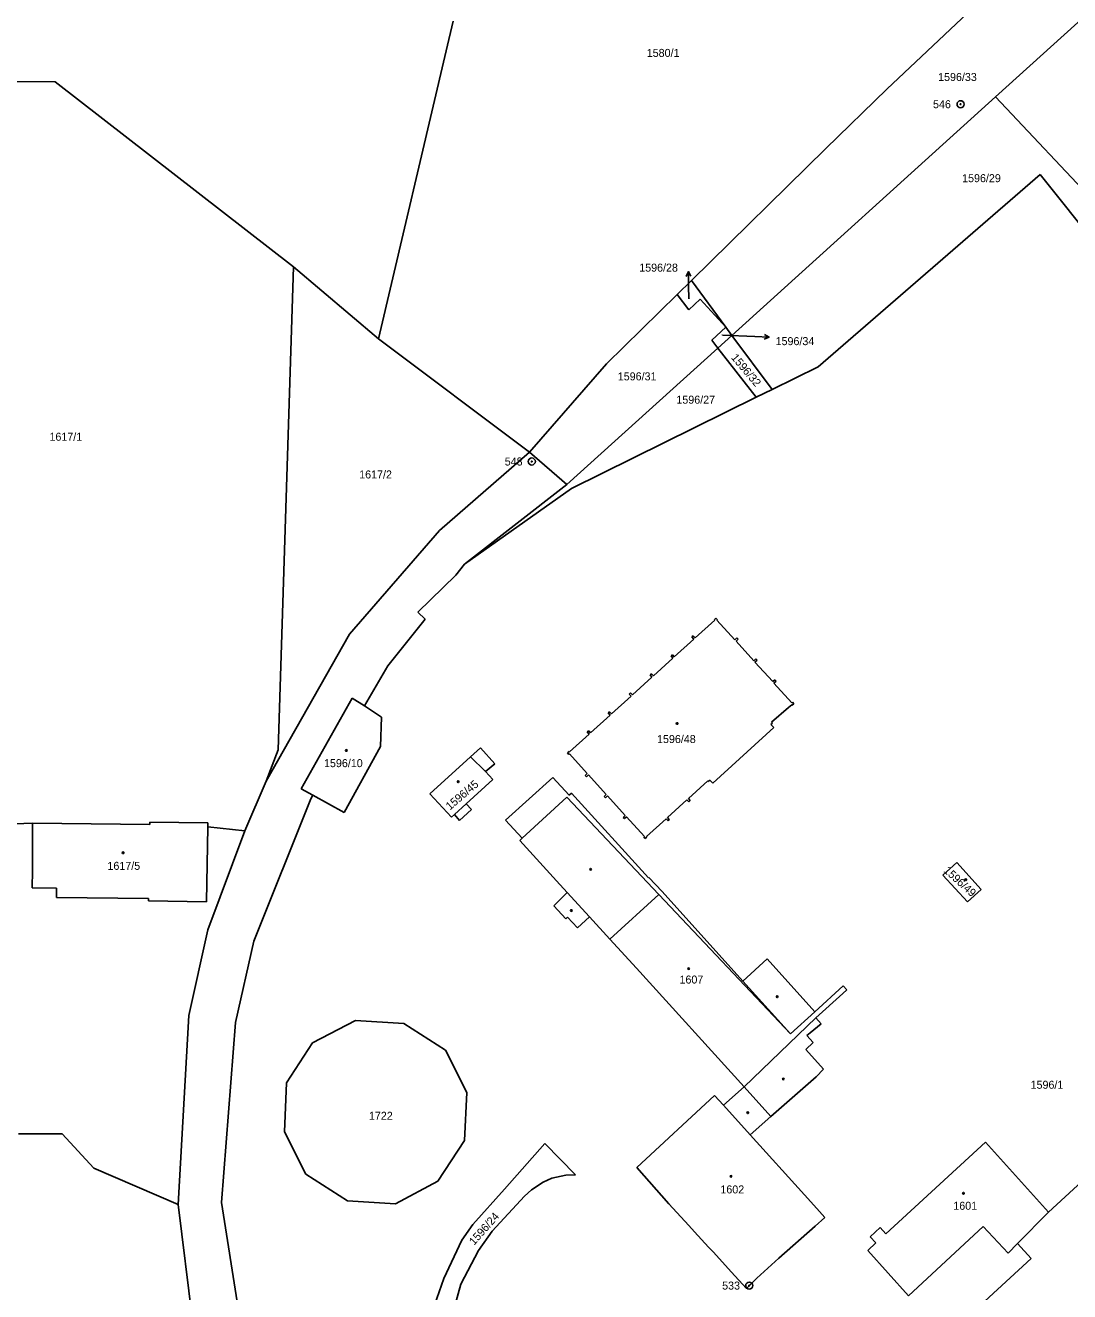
# Model space of a CAD drawing. Extents: x -763296 to -761805, y -1153670 to -1152034.
# Drawn here: x -762540.8 to -762319, y -1152808 to -1152539 of the extents above; entities that cross this region are included whole.
import ezdxf

# ---------------------------------------------------------------- set-up
doc = ezdxf.new("R2010")
doc.units = 0
for name, color, linetype in [('Vrstva 1', 7, 'Continuous'), ('Vrstva 16', 7, 'Continuous'), ('Vrstva 17', 7, 'Continuous'), ('Vrstva 18', 7, 'Continuous'), ('Vrstva 19', 7, 'Continuous'), ('Vrstva 24', 7, 'Continuous'), ('Vrstva 25', 7, 'Continuous'), ('Vrstva 4', 7, 'Continuous')]:
    doc.layers.add(name, color=color, linetype=linetype)

msp = doc.modelspace()

# ---------------------------------------------------------------- linework, layer by layer
at = {"layer": 'Vrstva 1'}
for p, q in [((-762281.64, -1152506.08), (-762334.74, -1152554.22)), ((-762357.84, -1152552.56), (-762327.69, -1152524.15)), ((-762451.46, -1152544.43), (-762449.99, -1152538.18)), ((-762465.85, -1152605.61), (-762451.46, -1152544.43)), ((-762563.28, -1152550.87), (-762534.53, -1152551.03)), ((-762534.53, -1152551.03), (-762483.9, -1152590.32)), ((-762370.78, -1152565.17), (-762357.84, -1152552.56)), ((-762334.74, -1152554.22), (-762390.74, -1152604.87)), ((-762334.74, -1152554.22), (-762311.03, -1152579.45)), ((-762399.32, -1152593.19), (-762370.78, -1152565.17)), ((-762372.45, -1152611.55), (-762325.29, -1152570.73)), ((-762325.29, -1152570.73), (-762304.85, -1152596.27)), ((-762483.9, -1152590.32), (-762487.15, -1152692.86)), ((-762483.9, -1152590.32), (-762465.85, -1152605.61)), ((-762399.32, -1152593.19), (-762402.39, -1152596.21)), ((-762399.32, -1152593.19), (-762392.03, -1152603.14)), ((-762402.39, -1152596.21), (-762417.4, -1152610.95)), ((-762399.93, -1152599.44), (-762402.39, -1152596.21)), ((-762397.51, -1152597.2), (-762399.93, -1152599.44)), ((-762397.51, -1152597.2), (-762392.03, -1152603.14)), ((-762395.01, -1152605.89), (-762392.03, -1152603.14)), ((-762390.74, -1152604.87), (-762393.71, -1152607.56)), ((-762392.03, -1152603.14), (-762390.74, -1152604.87)), ((-762390.74, -1152604.87), (-762382.19, -1152616.35)), ((-762465.85, -1152605.61), (-762433.74, -1152629.71)), ((-762393.71, -1152607.56), (-762425.78, -1152636.56)), ((-762393.71, -1152607.56), (-762395.01, -1152605.89)), ((-762385.59, -1152618.03), (-762393.71, -1152607.56)), ((-762417.4, -1152610.95), (-762433.74, -1152629.71)), ((-762382.19, -1152616.35), (-762372.45, -1152611.55)), ((-762424.84, -1152637.36), (-762385.59, -1152618.03)), ((-762385.59, -1152618.03), (-762382.19, -1152616.35)), ((-762433.74, -1152629.71), (-762452.83, -1152646.28)), ((-762425.78, -1152636.56), (-762433.74, -1152629.71)), ((-762425.78, -1152636.56), (-762447.55, -1152653.45)), ((-762447.55, -1152653.45), (-762424.84, -1152637.36)), ((-762452.83, -1152646.28), (-762472.01, -1152668.31)), ((-762447.55, -1152653.45), (-762449.4, -1152655.83)), ((-762449.4, -1152655.83), (-762457.48, -1152663.67)), ((-762457.48, -1152663.67), (-762455.94, -1152665.15)), ((-762455.94, -1152665.15), (-762463.84, -1152675.06)), ((-762394.37, -1152665.32), (-762398.54, -1152669.12)), ((-762394.14, -1152664.93), (-762394.47, -1152665.21)), ((-762394.47, -1152665.21), (-762394.37, -1152665.32)), ((-762393.84, -1152665.25), (-762394.14, -1152664.93)), ((-762393.95, -1152665.35), (-762393.84, -1152665.25)), ((-762390.13, -1152669.53), (-762393.95, -1152665.35)), ((-762472.01, -1152668.31), (-762489.68, -1152699.53)), ((-762398.85, -1152669.38), (-762402.98, -1152673.15)), ((-762398.95, -1152668.69), (-762399.24, -1152668.93)), ((-762399.24, -1152668.93), (-762398.85, -1152669.38)), ((-762398.54, -1152669.12), (-762398.95, -1152668.69)), ((-762389.69, -1152669.13), (-762390.13, -1152669.53)), ((-762389.87, -1152669.82), (-762389.43, -1152669.41)), ((-762389.43, -1152669.41), (-762389.69, -1152669.13)), ((-762386.12, -1152673.97), (-762389.87, -1152669.82)), ((-762463.84, -1152675.06), (-762468.82, -1152683.56)), ((-762403.29, -1152673.42), (-762407.42, -1152677.19)), ((-762403.38, -1152672.72), (-762403.67, -1152672.96)), ((-762403.67, -1152672.96), (-762403.29, -1152673.42)), ((-762402.98, -1152673.15), (-762403.38, -1152672.72)), ((-762385.67, -1152673.58), (-762386.12, -1152673.97)), ((-762385.85, -1152674.27), (-762385.41, -1152673.86)), ((-762382.08, -1152678.41), (-762385.85, -1152674.27)), ((-762385.41, -1152673.86), (-762385.67, -1152673.58)), ((-762407.73, -1152677.45), (-762411.87, -1152681.22)), ((-762407.83, -1152676.76), (-762408.12, -1152677)), ((-762408.12, -1152677), (-762407.73, -1152677.45)), ((-762407.42, -1152677.19), (-762407.83, -1152676.76)), ((-762381.65, -1152678.01), (-762382.08, -1152678.41)), ((-762381.81, -1152678.71), (-762381.38, -1152678.29)), ((-762378.02, -1152682.9), (-762381.81, -1152678.71)), ((-762381.38, -1152678.29), (-762381.65, -1152678.01)), ((-762482.24, -1152701.14), (-762471.39, -1152681.91)), ((-762471.39, -1152681.91), (-762468.82, -1152683.56)), ((-762412.18, -1152681.48), (-762416.32, -1152685.25)), ((-762412.28, -1152680.79), (-762412.57, -1152681.04)), ((-762412.57, -1152681.04), (-762412.18, -1152681.48)), ((-762411.87, -1152681.22), (-762412.28, -1152680.79)), ((-762377.9, -1152682.8), (-762378.02, -1152682.9)), ((-762377.95, -1152683.41), (-762377.62, -1152683.11)), ((-762377.62, -1152683.11), (-762377.9, -1152682.8)), ((-762468.82, -1152683.56), (-762465.15, -1152685.93)), ((-762416.63, -1152685.52), (-762420.76, -1152689.28)), ((-762416.72, -1152684.81), (-762417.02, -1152685.06)), ((-762417.02, -1152685.06), (-762416.63, -1152685.52)), ((-762416.32, -1152685.25), (-762416.72, -1152684.81)), ((-762382.33, -1152687.01), (-762378.74, -1152683.92)), ((-762378.74, -1152683.92), (-762378.04, -1152683.31)), ((-762378.04, -1152683.31), (-762377.95, -1152683.41)), ((-762465.15, -1152685.93), (-762465.37, -1152692.18)), ((-762394.82, -1152699.95), (-762381.86, -1152688.18)), ((-762382.47, -1152687.54), (-762382.13, -1152687.24)), ((-762381.86, -1152688.18), (-762382.47, -1152687.54)), ((-762382.13, -1152687.24), (-762382.33, -1152687.01)), ((-762421.07, -1152689.54), (-762425.23, -1152693.35)), ((-762421.16, -1152688.83), (-762421.46, -1152689.09)), ((-762421.46, -1152689.09), (-762421.07, -1152689.54)), ((-762420.76, -1152689.28), (-762421.16, -1152688.83)), ((-762487.15, -1152692.86), (-762489.68, -1152699.53)), ((-762465.37, -1152692.18), (-762473.14, -1152706.19)), ((-762446.26, -1152694.38), (-762444.18, -1152692.48)), ((-762444.18, -1152692.48), (-762441.09, -1152695.84)), ((-762425.34, -1152693.24), (-762425.67, -1152693.52)), ((-762425.67, -1152693.52), (-762425.39, -1152693.85)), ((-762425.39, -1152693.85), (-762425.26, -1152693.76)), ((-762425.23, -1152693.35), (-762425.34, -1152693.24)), ((-762425.26, -1152693.76), (-762421.48, -1152697.95)), ((-762454.88, -1152702.24), (-762446.26, -1152694.38)), ((-762441.09, -1152695.84), (-762443.07, -1152697.52)), ((-762441.54, -1152699.2), (-762447.19, -1152704.36)), ((-762443.07, -1152697.52), (-762441.54, -1152699.2)), ((-762428.78, -1152698.75), (-762438.83, -1152707.85)), ((-762425.34, -1152702.54), (-762428.78, -1152698.75)), ((-762421.48, -1152697.95), (-762421.91, -1152698.35)), ((-762421.91, -1152698.35), (-762421.65, -1152698.63)), ((-762421.65, -1152698.63), (-762421.21, -1152698.23)), ((-762421.21, -1152698.23), (-762417.46, -1152702.38)), ((-762395.76, -1152699.62), (-762395.43, -1152699.3)), ((-762395.43, -1152699.3), (-762394.82, -1152699.95)), ((-762489.68, -1152699.53), (-762494.2, -1152710.06)), ((-762479.75, -1152702.52), (-762482.24, -1152701.14)), ((-762399.99, -1152703.22), (-762395.86, -1152699.5)), ((-762395.86, -1152699.5), (-762395.76, -1152699.62)), ((-762492.32, -1152733.53), (-762480.19, -1152703.28)), ((-762480.19, -1152703.28), (-762479.75, -1152702.52)), ((-762473.14, -1152706.19), (-762479.75, -1152702.52)), ((-762450.31, -1152707.21), (-762454.88, -1152702.24)), ((-762447.19, -1152704.36), (-762446.06, -1152705.59)), ((-762424.84, -1152702.12), (-762425.34, -1152702.54)), ((-762408.46, -1152720.09), (-762424.84, -1152702.12)), ((-762417.46, -1152702.38), (-762417.88, -1152702.79)), ((-762417.88, -1152702.79), (-762417.61, -1152703.07)), ((-762417.61, -1152703.07), (-762417.18, -1152702.67)), ((-762417.18, -1152702.67), (-762413.42, -1152706.84)), ((-762404.44, -1152707.25), (-762400.3, -1152703.49)), ((-762400.3, -1152703.49), (-762399.9, -1152703.94)), ((-762399.61, -1152703.68), (-762399.99, -1152703.22)), ((-762399.9, -1152703.94), (-762399.61, -1152703.68)), ((-762449.7, -1152706.66), (-762450.31, -1152707.21)), ((-762448.58, -1152707.88), (-762449.7, -1152706.66)), ((-762446.06, -1152705.59), (-762448.58, -1152707.88)), ((-762413.42, -1152706.84), (-762413.84, -1152707.24)), ((-762413.84, -1152707.24), (-762413.59, -1152707.51)), ((-762413.59, -1152707.51), (-762413.14, -1152707.12)), ((-762413.14, -1152707.12), (-762409.35, -1152711.3)), ((-762404.05, -1152707.71), (-762404.44, -1152707.25)), ((-762539.34, -1152708.5), (-762546.77, -1152708.77)), ((-762514.4, -1152708.72), (-762539.34, -1152708.5)), ((-762539.34, -1152708.5), (-762539.32, -1152718.51)), ((-762514.39, -1152708.22), (-762514.4, -1152708.72)), ((-762502.07, -1152708.43), (-762514.39, -1152708.22)), ((-762502.38, -1152725.17), (-762502.09, -1152709.28)), ((-762502.09, -1152709.28), (-762502.07, -1152708.43)), ((-762494.2, -1152710.06), (-762502.09, -1152709.28)), ((-762502.04, -1152731.13), (-762494.2, -1152710.06)), ((-762438.83, -1152707.85), (-762435.29, -1152711.67)), ((-762408.91, -1152711.32), (-762404.73, -1152707.52)), ((-762404.73, -1152707.52), (-762404.31, -1152707.95)), ((-762404.31, -1152707.95), (-762404.05, -1152707.71)), ((-762435.8, -1152712.14), (-762435.29, -1152711.67)), ((-762428.02, -1152720.7), (-762435.8, -1152712.14)), ((-762409.35, -1152711.3), (-762409.44, -1152711.4)), ((-762409.44, -1152711.4), (-762409.14, -1152711.72)), ((-762409.14, -1152711.72), (-762408.83, -1152711.44)), ((-762408.83, -1152711.44), (-762408.91, -1152711.32)), ((-762345.91, -1152719.48), (-762342.99, -1152716.85)), ((-762342.99, -1152716.85), (-762337.77, -1152722.58)), ((-762539.32, -1152718.51), (-762539.38, -1152722.19)), ((-762425.74, -1152723.19), (-762428.02, -1152720.7)), ((-762408.36, -1152720.01), (-762408.46, -1152720.09)), ((-762405.58, -1152723), (-762408.36, -1152720.01)), ((-762340.67, -1152725.2), (-762345.91, -1152719.48)), ((-762539.38, -1152722.19), (-762534.2, -1152722.27)), ((-762534.2, -1152722.27), (-762534.23, -1152724.25)), ((-762425.74, -1152723.19), (-762428.57, -1152725.99)), ((-762388.45, -1152741.99), (-762405.58, -1152723)), ((-762337.77, -1152722.58), (-762340.67, -1152725.2)), ((-762534.23, -1152724.25), (-762514.66, -1152724.44)), ((-762514.66, -1152724.44), (-762514.67, -1152724.97)), ((-762514.67, -1152724.97), (-762502.38, -1152725.17)), ((-762428.57, -1152725.99), (-762426, -1152728.75)), ((-762426, -1152728.75), (-762425.64, -1152728.42)), ((-762425.64, -1152728.42), (-762423.58, -1152730.67)), ((-762423.58, -1152730.67), (-762421.03, -1152728.33)), ((-762416.67, -1152733.1), (-762421.03, -1152728.33)), ((-762506.09, -1152749.33), (-762502.04, -1152731.13)), ((-762492.32, -1152733.53), (-762496.17, -1152750.77)), ((-762416.67, -1152733.1), (-762411, -1152739.29)), ((-762411, -1152739.29), (-762388.13, -1152764.44)), ((-762383.24, -1152737.28), (-762388.45, -1152741.99)), ((-762373.11, -1152748.52), (-762383.24, -1152737.28)), ((-762367.09, -1152743.02), (-762373.11, -1152748.52)), ((-762372.91, -1152749.82), (-762367.17, -1152744.61)), ((-762367.17, -1152744.61), (-762366.35, -1152743.86)), ((-762366.35, -1152743.86), (-762367.09, -1152743.02)), ((-762508.36, -1152789.42), (-762506.09, -1152749.33)), ((-762470.69, -1152750.4), (-762479.81, -1152755.1)), ((-762460.47, -1152751), (-762470.69, -1152750.4)), ((-762371.79, -1152751.06), (-762372.91, -1152749.82)), ((-762496.17, -1152750.77), (-762499.2, -1152789.04)), ((-762460.47, -1152751), (-762451.62, -1152756.7)), ((-762374.82, -1152753.54), (-762374.12, -1152752.96)), ((-762374.12, -1152752.96), (-762371.79, -1152751.06)), ((-762479.81, -1152755.1), (-762485.39, -1152763.63)), ((-762375.07, -1152756.55), (-762373.51, -1152755.04)), ((-762373.51, -1152755.04), (-762374.82, -1152753.54)), ((-762451.62, -1152756.7), (-762447.02, -1152765.68)), ((-762371.31, -1152760.71), (-762375.07, -1152756.55)), ((-762372.87, -1152762.36), (-762371.31, -1152760.71)), ((-762485.39, -1152763.63), (-762485.82, -1152774)), ((-762382.45, -1152770.73), (-762372.87, -1152762.36)), ((-762447.02, -1152765.68), (-762447.54, -1152775.89)), ((-762410.91, -1152781.62), (-762394.44, -1152766.33)), ((-762394.44, -1152766.33), (-762392.51, -1152768.38)), ((-762388.13, -1152764.44), (-762392.51, -1152768.38)), ((-762392.51, -1152768.38), (-762386.84, -1152774.68)), ((-762386.84, -1152774.68), (-762382.45, -1152770.73)), ((-762532.99, -1152774.42), (-762542.3, -1152774.42)), ((-762526.31, -1152781.74), (-762532.99, -1152774.42)), ((-762485.82, -1152774), (-762481.28, -1152783)), ((-762323.47, -1152791.06), (-762304.18, -1152773.27)), ((-762447.54, -1152775.89), (-762453.19, -1152784.48)), ((-762439.08, -1152786.17), (-762430.49, -1152776.49)), ((-762430.49, -1152776.49), (-762423.95, -1152783.13)), ((-762386.84, -1152774.68), (-762375.36, -1152787.41)), ((-762358.06, -1152795.67), (-762336.9, -1152776.19)), ((-762336.9, -1152776.19), (-762323.47, -1152791.06)), ((-762508.36, -1152789.42), (-762526.31, -1152781.74)), ((-762404.12, -1152789.3), (-762410.91, -1152781.62)), ((-762481.28, -1152783), (-762472.43, -1152788.7)), ((-762462.21, -1152789.3), (-762453.19, -1152784.48)), ((-762430.82, -1152784.7), (-762433.34, -1152786.3)), ((-762428.97, -1152783.85), (-762430.82, -1152784.7)), ((-762426, -1152783.24), (-762428.97, -1152783.85)), ((-762423.95, -1152783.13), (-762426, -1152783.24)), ((-762445.79, -1152793.67), (-762439.08, -1152786.17)), ((-762434.84, -1152787.68), (-762441.66, -1152795.08)), ((-762433.34, -1152786.3), (-762434.84, -1152787.68)), ((-762375.36, -1152787.41), (-762372.72, -1152790.32)), ((-762508.36, -1152789.42), (-762504.64, -1152819.5)), ((-762499.2, -1152789.04), (-762495.62, -1152811.48)), ((-762472.43, -1152788.7), (-762462.21, -1152789.3)), ((-762399.9, -1152793.94), (-762404.12, -1152789.3)), ((-762372.72, -1152790.32), (-762371.03, -1152792.19)), ((-762371.03, -1152792.19), (-762373.07, -1152794.05)), ((-762323.47, -1152791.06), (-762330.08, -1152797.75)), ((-762448.1, -1152797.01), (-762445.79, -1152793.67)), ((-762441.66, -1152795.08), (-762444.61, -1152799.19)), ((-762398.69, -1152795.27), (-762399.9, -1152793.94)), ((-762395.72, -1152798.53), (-762398.69, -1152795.27)), ((-762373.07, -1152794.05), (-762380.8, -1152800.84)), ((-762361.38, -1152796.29), (-762359.29, -1152794.34)), ((-762359.29, -1152794.34), (-762358.06, -1152795.67)), ((-762337.37, -1152794.13), (-762353.25, -1152808.84)), ((-762332.1, -1152799.8), (-762337.37, -1152794.13)), ((-762451.93, -1152805.15), (-762448.1, -1152797.01)), ((-762394.69, -1152799.57), (-762395.72, -1152798.53)), ((-762361.9, -1152799.22), (-762360.15, -1152797.61)), ((-762360.15, -1152797.61), (-762361.38, -1152796.29)), ((-762330.08, -1152797.75), (-762332.1, -1152799.8)), ((-762330.08, -1152797.75), (-762327.17, -1152800.94)), ((-762444.61, -1152799.19), (-762448.3, -1152806.34)), ((-762390.93, -1152803.73), (-762394.69, -1152799.57)), ((-762380.8, -1152800.84), (-762385.46, -1152805.08)), ((-762353.25, -1152808.84), (-762361.9, -1152799.22)), ((-762349.07, -1152820.98), (-762327.17, -1152800.94)), ((-762387.68, -1152807.32), (-762390.93, -1152803.73)), ((-762453.95, -1152810.83), (-762451.93, -1152805.15)), ((-762448.3, -1152806.34), (-762450.74, -1152815.01)), ((-762385.46, -1152805.08), (-762387.68, -1152807.32))]:
    msp.add_line(p, q, dxfattribs=at)
at = {"layer": 'Vrstva 16'}
for p, q in [((-762399.991, -1152591.34), (-762399.94, -1152594.34)), ((-762399.89, -1152597.09), (-762399.94, -1152594.34)), ((-762392.73, -1152604.85), (-762385.86, -1152605.13)), ((-762382.862, -1152605.251), (-762385.86, -1152605.13))]:
    msp.add_line(p, q, dxfattribs=at)
for points in [[(-762400.474, -1152592.349), (-762399.991, -1152591.34), (-762399.474, -1152592.332)], [(-762383.841, -1152604.711), (-762382.862, -1152605.251), (-762383.882, -1152605.71)]]:
    msp.add_lwpolyline(points, dxfattribs=at)
at = {"layer": 'Vrstva 24'}
for centre, radius in [((-762342.18, -1152555.78), 0.75), ((-762342.18, -1152555.78), 0.1), ((-762433.25, -1152631.66), 0.75), ((-762433.25, -1152631.66), 0.1), ((-762387.07, -1152806.67), 0.75), ((-762387.07, -1152806.67), 0.1)]:
    msp.add_circle(centre, radius, dxfattribs=at)
at = {"layer": 'Vrstva 25'}
for centre in [(-762402.39, -1152687.3), (-762472.66, -1152693.02), (-762448.88, -1152699.66), (-762520.07, -1152714.75), (-762420.76, -1152718.26), (-762341.07, -1152720.47), (-762424.87, -1152727.02), (-762399.95, -1152739.35), (-762381.13, -1152745.32), (-762379.81, -1152762.8), (-762387.37, -1152769.96), (-762390.95, -1152783.47), (-762341.57, -1152787.06)]:
    msp.add_circle(centre, 0.175, dxfattribs=at)
at = {"layer": 'Vrstva 4'}
for p, q in [((-762446.26, -1152694.38), (-762443.07, -1152697.52)), ((-762447.19, -1152704.36), (-762449.7, -1152706.66)), ((-762425.8, -1152702.94), (-762435.29, -1152711.67)), ((-762425.8, -1152702.94), (-762406.26, -1152723.62)), ((-762425.74, -1152723.19), (-762421.03, -1152728.33)), ((-762416.67, -1152733.1), (-762406.26, -1152723.62)), ((-762406.26, -1152723.62), (-762378.27, -1152753.23)), ((-762378.27, -1152753.23), (-762388.45, -1152741.99)), ((-762388.13, -1152764.44), (-762372.91, -1152749.82)), ((-762373.11, -1152748.52), (-762378.27, -1152753.23)), ((-762382.45, -1152770.73), (-762388.13, -1152764.44))]:
    msp.add_line(p, q, dxfattribs=at)

# ---------------------------------------------------------------- texts
at = {"layer": 'Vrstva 16'}
for s, p in [('1596/28', (-762410.437, -1152591.34)), ('1596/34', (-762381.467, -1152606.95))]:
    msp.add_text(s, height=1.7, dxfattribs=at).set_placement(p)
at = {"layer": 'Vrstva 17'}
for s, p in [('546', (-762348.027, -1152556.63)), ('548', (-762439.004, -1152632.51)), ('533', (-762392.824, -1152807.52))]:
    msp.add_text(s, height=1.7, dxfattribs=at).set_placement(p)
at = {"layer": 'Vrstva 18'}
for s, height, p in [('1580/1', 1.7, (-762408.837, -1152545.74)), ('1596/33', 1.7, (-762346.945, -1152550.85)), ('1596/29', 1.7, (-762341.844, -1152572.34)), ('1596/28', 0.1, (-762400.161, -1152597.09)), ('1596/34', 0.1, (-762393, -1152604.85)), ('1596/31', 1.7, (-762414.99, -1152614.43)), ('1596/27', 1.7, (-762402.544, -1152619.38)), ('1617/1', 1.7, (-762535.708, -1152627.25)), ('1617/2', 1.7, (-762469.92, -1152635.26)), ('1596/1', 1.7, (-762327.303, -1152764.87)), ('1722', 1.7, (-762467.853, -1152771.46))]:
    msp.add_text(s, height=height, dxfattribs=at).set_placement(p)
for s, rotation, p in [('1596/32', 310.25665, (-762391.019, -1152609.655)), ('1596/24', 48.41493, (-762445.503, -1152798.219))]:
    msp.add_text(s, height=1.7, rotation=rotation, dxfattribs=at).set_placement(p)
at = {"layer": 'Vrstva 19'}
for s, p in [('1596/48', (-762406.651, -1152691.45)), ('1596/10', (-762477.389, -1152696.57)), ('1617/5', (-762523.393, -1152718.38)), ('1607', (-762401.882, -1152742.53)), ('1602', (-762393.196, -1152787.1)), ('1601', (-762343.714, -1152790.57))]:
    msp.add_text(s, height=1.7, dxfattribs=at).set_placement(p)
for s, rotation, p in [('1596/45', 40.50812, (-762450.645, -1152705.79)), ('1596/49', 317.76239, (-762345.919, -1152718.708))]:
    msp.add_text(s, height=1.7, rotation=rotation, dxfattribs=at).set_placement(p)

doc.saveas('drawing.dxf')
